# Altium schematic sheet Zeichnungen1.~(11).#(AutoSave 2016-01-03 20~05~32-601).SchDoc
size A4; PageSetup: Record=PageOptions¦CenterHorizontal=True¦CenterVertical=True¦PrintScale=1.00¦XCorrection=1.00¦YCorrection=1.00¦PrintKind=0¦BorderSize=5000000¦LeftOffset=0¦BottomOffset=0¦Orientation=2¦PaperLength=1000¦PaperWidth=1000¦Scale=100¦PaperSource=7¦PrintQuality=-3¦MediaType=1¦DitherType=10¦PrintScaleMode=1¦PaperKind=A4¦PaperIndex=9
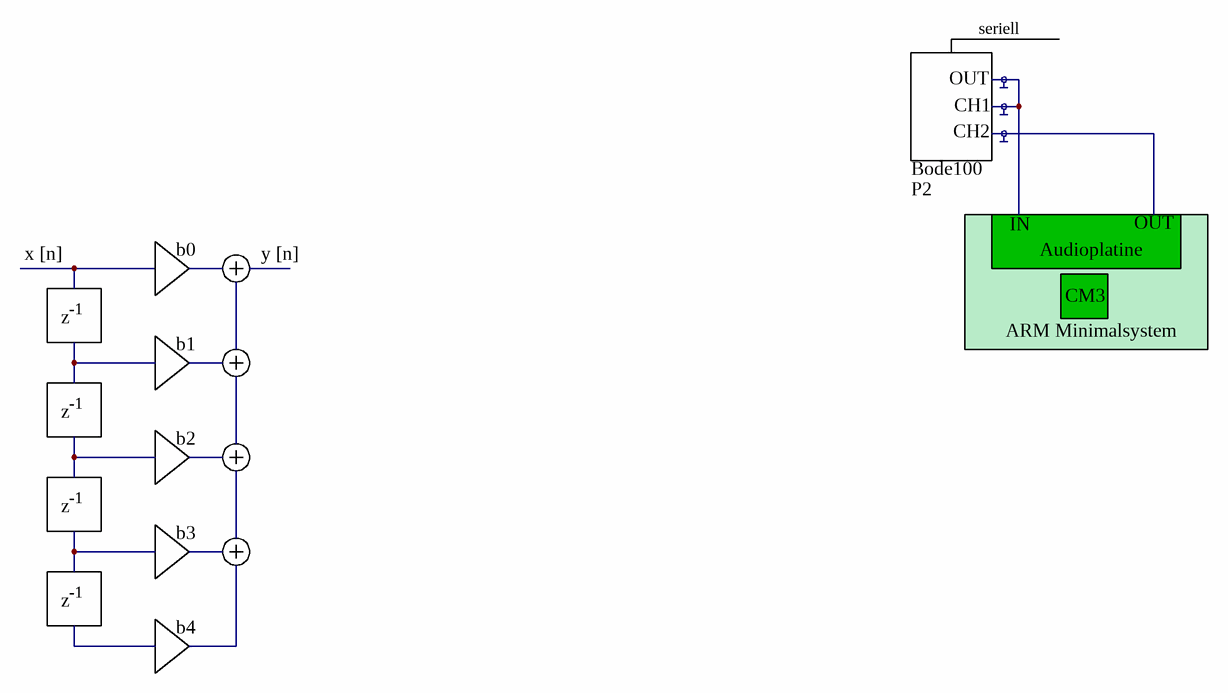
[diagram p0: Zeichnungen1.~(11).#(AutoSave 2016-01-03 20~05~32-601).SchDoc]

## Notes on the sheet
- seriell
- OUT
- CH2
- CH1
- Bode100
- P2
- x [n]
- b0
- y [n]
- IN
- Audioplatine
- z
- -1
- b1
- ARM Minimalsystem
- CM3
- b2
- b3
- b4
